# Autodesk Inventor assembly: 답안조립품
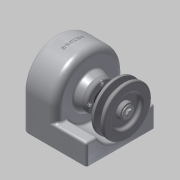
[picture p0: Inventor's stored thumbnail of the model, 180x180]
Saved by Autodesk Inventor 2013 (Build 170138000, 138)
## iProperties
Created: 2015-02
Part Number: 답안조립품
Document SubType Name: Assembly
Designer: Administrator
Author: Administrator
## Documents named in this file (14)
- C:\Users\Administrator\Desktop\450216V1004\답안조립품.iam
- C:\Users\Administrator\Desktop\450216V1004\본체.ipt
- C:\Users\Administrator\Desktop\450216V1004\축.ipt
- C:\Users\Administrator\Desktop\450216V1004\키4x4.ipt
- C:\Users\Administrator\Desktop\450216V1004\V-밸트풀리.ipt
- C:\Users\Administrator\Desktop\450216V1004\키5x5.ipt
- C:\Users\Administrator\Desktop\450216V1004\스퍼기어.ipt
- C:\Users\Administrator\Desktop\450216V1004\베어링 6001.ipt
- C:\Users\Administrator\Desktop\450216V1004\축커버.ipt
- C:\Users\Administrator\Desktop\450216V1004\오일실.ipt
- C:\Users\Administrator\Desktop\450216V1004\와샤.ipt
- C:\Users\Administrator\Desktop\450216V1004\M3x0.5.ipt
- C:\Users\Administrator\Desktop\450216V1004\M5x0.8.ipt
- M5x0.8.ipt
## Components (6 placed, 3 different names)
1. V-밸트풀리:1
2. M5x0.8:1 — 각도:1
3. M3x0.5:1
4. M3x0.5:2
5. M3x0.5:3
6. M3x0.5:4
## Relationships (1: Angle 1)
- 각도:1 [Angle]: M5x0.8:1
